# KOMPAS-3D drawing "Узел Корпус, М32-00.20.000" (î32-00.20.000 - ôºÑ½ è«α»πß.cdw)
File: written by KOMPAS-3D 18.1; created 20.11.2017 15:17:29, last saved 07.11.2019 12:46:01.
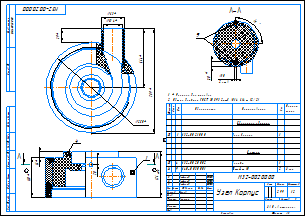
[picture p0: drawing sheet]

Sheet 1: A3, landscape

Document properties: Полное имя файла: D:\Magna\Магна Ins\Магна ins 32\Для Караби\М32-00.20.000 - Узел Корпус.cdw; Масса: 2.99454

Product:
- Part/product: Узел Корпус  | designation М32-00.20.000  | pos. 0
    Масса: 2.99454
    Раздел спецификации: Сборочные единицы
    Форматы листов документа: A3
    source file: М32-00.20.000 - Корпус.cdw
  - Component [assembly]: Узел Кольцо  | designation М32-00.21.000  | pos. 1  | Масса: 1.30083; Раздел спецификации: Сборочные единицы; Форматы листов документа: A3; Зона: 2A; source file: М32-00.21.000 - Кольцо.cdw, М32-00.21.000 - Узел Кольцо.a3d, М32-00.21.000-01 - Кольцо.cdw
  - Component [detail]: Корпус  | designation М32-00.20.002  | pos. 4
      Материал: Полипропилен  ГОСТ 26996-86 (density 900 kg/m3)
      Масса: 1.66168
      Раздел спецификации: Детали
      Форматы листов документа: A3
      Зона: 2A
      source file: М32-00.20.002 - Корпус.cdw, М32-00.20.002 - Корпус.m3d
  - Component [detail]: Штифт 10  | designation М40-00.30.001  | pos. 10  | Масса: 0.0172762; Раздел спецификации: Детали; Форматы листов документа: A4; source file: М40-00.30.001 - Штифт 10.m3d
  - Component [detail]: Штифт 10  | designation М40-00.30.001  | pos. 9  | Масса: 0.0172762; Раздел спецификации: Детали; Форматы листов документа: A4; source file: М40-00.30.001 - Штифт 10.m3d

Title block, sheet 1: Наименование: Узел Корпус; designation: М32-00.20.000; Масса: 2,99; scale: 1:2; Количество листов документа: 1; organisation: ЗАО «Астерион»; Форматы листов документа: A3; stored path: D:\Отработать\Магна 40\3Д\М40-00.20.000 - Корпус.cdw; Разработал: Милов; Т. контр.: Лучихин

Views: Вид 1, Местный разрез 1, Вид:1, Проекционный вид 3, Разрез А-А, Вид 5
Referenced files in D:\Magna\Магна Ins\Магна ins 32\Для Караби\: М32-00.20.000 - Узел Корпус.a3d, М32-00.21.000 - Узел Кольцо.a3d, М32-00.21.000-01 - Кольцо.cdw, М32-00.21.000 - Кольцо.cdw, М32-00.20.002 - Корпус.m3d, М32-00.20.002 - Корпус.cdw, М40-00.30.001 - Штифт 10.m3d, М32-00.21.001 - Кольцо.m3d
Referenced files in D:\Отработать\Магна 40\3Д\: М40-00.20.000 - Корпус.a3d, Труба 63х5.8 PN10.m3d
Referenced files in Z:\Магна\Магна Ins\Магна ins 32\: М32-00.20.000 - Корпус.a3d, М32-00.20.001 - Стопор.m3d, М32-00.20.003 - Крышка.m3d, М32-00.20.002 - Корпус.m3d
Referenced files in D:\1 ПКИ 3D\Полипропиленовые фитинги, трубы\Трубы\: Труба 63 PN10 S=5,8 FV PPR ф. FV PLAST.m3d
Referenced files in Z:\1 ПКИ 3D\Полипропиленовые фитинги, трубы\Трубы\: Труба 63 PN10 S=5,8 FV PPR ф. FV PLAST.m3d
Referenced files in \\192.168.87.28\Konstructor_doc\Магна\Магна Ins\Магна ins 32\: М32-00.21.001 - Кольцо.m3d
Referenced files in D:\Magna\Магна Ins\Магна ins 32\: М32-00.20.002 - Корпус.m3d
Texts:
  Заим.
  Узел Кольцо
  Корпус
  Штифт 10
  Лифлянд
  Кольцо
  Труба 63 PN10 S=5,8 FV PPR ф. FV PLAST
Dimensions and other numbers on the sheet: 1; 126; 4; 16; 110; 2; 20; 51,4; 63; 250; 164; 289; 39; 10; 2 отв.; 30; 9; 1:2; 2,99; 01.07.2019; 12.07.2019; 3; 07.11.2019

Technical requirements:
  * Размеры для справок.
  Общие допуски ГОСТ 30893.2-mK (H14, h14,  t2/2).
